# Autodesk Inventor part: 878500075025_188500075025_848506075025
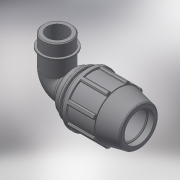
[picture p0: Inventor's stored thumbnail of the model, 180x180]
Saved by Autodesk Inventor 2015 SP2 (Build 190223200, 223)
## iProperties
Created: 2017-02
Part Number: 878500075025_188500075025_848506075025
Material: Generic
Description: PLASSON 90° ELBOW MALE ADAPTOR 75-2.1/2"
Document SubType Name: Modeling
Designer: KIM
Mass: 1366.09 g
Surface Area: 1816.46 cm^2
Volume: 1366.09 cm^3
Density: 1 g/cm^3
Appearance: Default
Author: KIM
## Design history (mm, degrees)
derived "87850.ipt"
feature "Solid1::87850.ipt"
tag "TaggingFeature1"
body "Solid1"
other parameters: "d2" = 75, "d4" = 17.25, "d5" = 51.75, "d7" = 132, "d9" = 29.57143, "d11" = 6.9, "d13" = 120 deg, "d14" = 97.5, "d15" = 12 deg, "d16" = 114.84, "d18" = 3.75, "d19" = 35 deg, "d20" = 17.5 deg, "d21" = 122.76, "d23" = 0, "d25" = 360 deg, "d27" = 2.64, "d33" = 1.5, "d42" = 76.59, "d43" = 3.96, "d46" = 2.25, "d51" = 207, "d68" = 13.8, "d72" = 105, "d73" = 72.226, "d75" = 83.0599, "d76" = 50.5582, "d77" = 33, "d79" = 28.8904, "d80" = 2.16678, "d83" = 0, "d84" = 0, "d91" = 99, "d93" = 137, "d94" = 72.226, "d95" = 50.5582, "d96" = 13.8, "d97" = 50 deg, "d98" = 3.45, "d99" = 111.3948, "d100" = 3.45, "d101" = 3.45, "d102" = 8.8, "d103" = 0, "d_" = 75, "E_" = 132, "A_" = 207, "l_" = 137, "A_1" = 105, "G_" = 72.226
